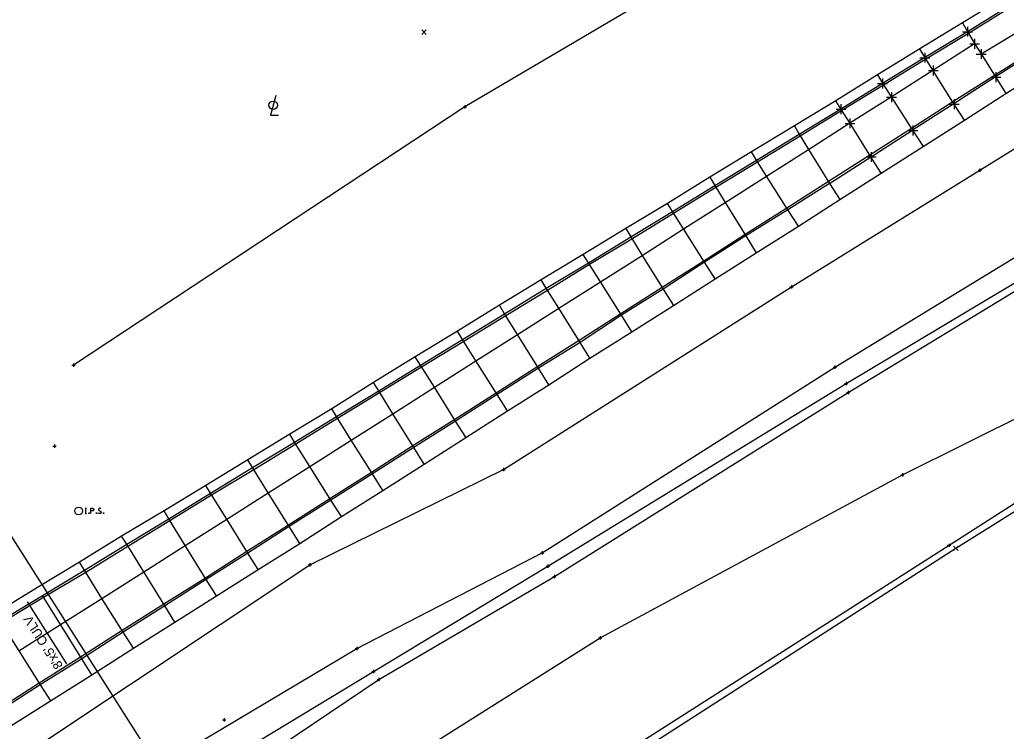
# Model space of a CAD drawing. Extents: x 207090 to 277928, y 600777 to 621109.
# Drawn here: x 261676.8 to 261977.3, y 611702.8 to 611919.6 of the extents above; entities that cross this region are included whole.
import ezdxf

# ---------------------------------------------------------------- set-up
doc = ezdxf.new("R2010")
doc.units = 0
for name, color, linetype in [('BR_X_SV_Abut', 7, 'Continuous'), ('DR_X_Culvert', 7, 'Continuous'), ('DR_X_Ditch', 7, 'Continuous'), ('DR_X_Text', 7, 'Continuous'), ('PM_P_Dotted_Line', 7, 'Continuous'), ('PM_P_Edge_Line', 7, 'Continuous'), ('PM_P_Lane_Line', 7, 'Continuous'), ('PM_P_Stop_Line', 7, 'Continuous'), ('PM_X_Edge_Line', 7, 'Continuous'), ('PV_X_EOP', 7, 'Continuous'), ('PV_X_Joint', 7, 'Continuous'), ('PV_X_Shoulder', 7, 'Continuous'), ('SC_ProfileRun2', 7, 'Continuous'), ('SV_X_LiDAR_Check_Spots', 7, 'Continuous'), ('SV_X_Terrain_Boundary', 7, 'Continuous'), ('SV_X_Toe_of_Slope', 7, 'Continuous')]:
    doc.layers.add(name, color=color, linetype=linetype)

msp = doc.modelspace()

# ---------------------------------------------------------------- linework, layer by layer
at = {"layer": 'BR_X_SV_Abut'}
msp.add_lwpolyline([(261754.78, 611896.47), (261753.2, 611890.49), (261755.57, 611890.49)], dxfattribs=at)
msp.add_circle((261753.99, 611893.52), 1.3, dxfattribs=at)
at = {"layer": 'DR_X_Culvert'}
msp.add_line((261715.99, 611696.51), (261667.47, 611772.86), dxfattribs=at)
at = {"layer": 'DR_X_Ditch'}
msp.add_lwpolyline([(261132.11, 611543.06), (261151.34, 611551.01), (261204.82, 611549.24), (261275.42, 611542.1), (261338.97, 611540.56), (261396.89, 611545.27), (261464.5, 611556.09), (261526.91, 611576.88), (261579.68, 611599.94), (261643.38, 611630.11), (261702.06, 611671.1), (261784.56, 611720.96), (261837.63, 611753.06), (261928.54, 611808.72), (261986.01, 611843.07), (262043.42, 611883.09), (262136.97, 611939.5), (262196.81, 611979.61), (262342.79, 612067.36), (262434.39, 612121.89), (262514.3, 612151.84), (262581.31, 612172.43), (262656.49, 612183.09)], dxfattribs=at)
at = {"layer": 'DR_X_Text'}
msp.add_line((261679.01, 611742.21), (261691, 611723.34), dxfattribs=at)
at = {"layer": 'PM_P_Dotted_Line'}
for points in [[(261696.72, 611770.7), (261697.08, 611770.7)], [(261696.72, 611769.1), (261697.08, 611769.1)], [(261696.9, 611769.1), (261696.9, 611770.7)], [(261697.86, 611769.31), (261697.92, 611769.31), (261697.95, 611769.28), (261697.98, 611769.23), (261697.98, 611769.17), (261697.95, 611769.12), (261697.92, 611769.1), (261697.86, 611769.1), (261697.83, 611769.12), (261697.79, 611769.17), (261697.79, 611769.23), (261697.83, 611769.28), (261697.86, 611769.31)], [(261698.47, 611769.1), (261698.47, 611770.7), (261699, 611770.7), (261699.05, 611770.68), (261699.13, 611770.66), (261699.16, 611770.63), (261699.19, 611770.61), (261699.24, 611770.54), (261699.27, 611770.48), (261699.29, 611770.38), (261699.29, 611770.23), (261699.28, 611770.18), (261699.26, 611770.1), (261699.22, 611770.02), (261699.17, 611769.98), (261699.14, 611769.95), (261699.08, 611769.93), (261699, 611769.91), (261698.47, 611769.91)], [(261700.11, 611769.31), (261700.16, 611769.31), (261700.2, 611769.28), (261700.23, 611769.23), (261700.23, 611769.17), (261700.2, 611769.12), (261700.16, 611769.1), (261700.11, 611769.1), (261700.08, 611769.12), (261700.04, 611769.17), (261700.04, 611769.23), (261700.08, 611769.28), (261700.11, 611769.31)], [(261701.48, 611770.58), (261701.45, 611770.61), (261701.42, 611770.63), (261701.32, 611770.67), (261701.2, 611770.7), (261701.11, 611770.7), (261701.08, 611770.7), (261700.94, 611770.66), (261700.81, 611770.58), (261700.74, 611770.48), (261700.72, 611770.38), (261700.72, 611770.3), (261700.74, 611770.2), (261700.83, 611770.12), (261701.43, 611769.74), (261701.49, 611769.69), (261701.51, 611769.64), (261701.53, 611769.56), (261701.53, 611769.49), (261701.52, 611769.41), (261701.51, 611769.36), (261701.49, 611769.3), (261701.46, 611769.25), (261701.44, 611769.21), (261701.41, 611769.17), (261701.38, 611769.15), (261701.33, 611769.12), (261701.3, 611769.11), (261701.2, 611769.1), (261701.05, 611769.1), (261700.95, 611769.12), (261700.8, 611769.21), (261700.72, 611769.28)], [(261702.29, 611769.31), (261702.35, 611769.31), (261702.38, 611769.28), (261702.41, 611769.23), (261702.41, 611769.17), (261702.38, 611769.12), (261702.35, 611769.1), (261702.29, 611769.1), (261702.26, 611769.12), (261702.23, 611769.17), (261702.23, 611769.23), (261702.26, 611769.28), (261702.29, 611769.31)]]:
    msp.add_lwpolyline(points, dxfattribs=at)
msp.add_circle((261694.71, 611769.89), 1.2, dxfattribs=at)
at = {"layer": 'PM_P_Edge_Line'}
for points in [[(261095.2, 611517.38), (261109.55, 611556.21), (261131.91, 611573.68), (261149.08, 611575.07), (261202.59, 611571.64), (261280.97, 611564.25), (261338.62, 611565.1), (261393.58, 611575.38), (261461.16, 611589.52), (261517.96, 611607.33), (261562.93, 611628.5), (261627.57, 611664.18), (261682.84, 611698.73), (261765.12, 611753.52), (261824.13, 611782.52), (261911.81, 611838.23), (261969.24, 611873.72), (262025.82, 611908.8), (262125.41, 611964.66), (262182.53, 612002.94), (262326.11, 612091.51)], [(261150.65, 611386.42), (261155.64, 611444.15), (261157.57, 611491.18), (261209.46, 611500.37), (261264.83, 611505.15), (261342.34, 611500.54), (261398.44, 611505.87), (261472.12, 611523.34), (261533.41, 611542.89), (261595.48, 611569.82), (261660.17, 611598), (261726.83, 611640.47), (261794.94, 611694.24), (261853.6, 611731.21), (261945.61, 611780.89), (262004.28, 611810.1), (262064.35, 611850.74), (262127.57, 611893.89), (262159.14, 611906.07), (262217.33, 611944.84), (262360.65, 612038.77)]]:
    msp.add_lwpolyline(points, dxfattribs=at)
at = {"layer": 'PM_P_Lane_Line'}
msp.add_lwpolyline([(261153.94, 611385.97), (261160.28, 611443.31), (261165.11, 611483.68), (261209.25, 611484.8), (261264.74, 611486.28), (261342.14, 611487.48), (261398.74, 611488.7), (261481.71, 611501.24), (261537, 611521.16), (261606, 611546.1), (261656.85, 611565.67), (261670.38, 611573.79), (261742.74, 611619.98), (261811.92, 611664.95), (261868.59, 611701.14), (261959.9, 611759.42), (262013.54, 611793.87), (262076.54, 611833.59), (262168.76, 611888.84), (262184.39, 611898.2), (262204.83, 611910.25), (262363.11, 611892.31)], dxfattribs=at)
at = {"layer": 'PM_P_Stop_Line'}
for p, q in [((261811.86, 611893.04), (261812.86, 611893.04)), ((261812.36, 611893.54), (261812.36, 611892.54)), ((261812.36, 611893.04), (261812.36, 611893.04)), ((261968.74, 611873.72), (261969.74, 611873.72)), ((261969.24, 611874.22), (261969.24, 611873.22)), ((261969.24, 611873.72), (261969.24, 611873.72)), ((261911.31, 611838.23), (261912.31, 611838.23)), ((261911.81, 611838.73), (261911.81, 611837.73)), ((261911.81, 611838.23), (261911.81, 611838.23)), ((261692.64, 611814.37), (261693.64, 611814.37)), ((261693.14, 611814.87), (261693.14, 611813.87)), ((261693.14, 611814.37), (261693.14, 611814.37)), ((261924.55, 611813.69), (261925.55, 611813.69)), ((261925.05, 611814.19), (261925.05, 611813.19)), ((261925.05, 611813.69), (261925.05, 611813.69)), ((261928.04, 611808.72), (261929.04, 611808.72)), ((261928.54, 611809.22), (261928.54, 611808.22)), ((261928.54, 611808.72), (261928.54, 611808.72)), ((261928.57, 611806.04), (261929.57, 611806.04)), ((261929.07, 611806.54), (261929.07, 611805.54)), ((261929.07, 611806.04), (261929.07, 611806.04)), ((261823.63, 611782.52), (261824.63, 611782.52)), ((261824.13, 611783.02), (261824.13, 611782.02)), ((261824.13, 611782.52), (261824.13, 611782.52)), ((261945.11, 611780.89), (261946.11, 611780.89)), ((261945.61, 611781.39), (261945.61, 611780.39)), ((261945.61, 611780.89), (261945.61, 611780.89)), ((261959.4, 611759.42), (261960.4, 611759.42)), ((261959.9, 611759.92), (261959.9, 611758.92)), ((261959.9, 611759.42), (261959.9, 611759.42)), ((261835.4, 611757.16), (261836.4, 611757.16)), ((261835.9, 611757.66), (261835.9, 611756.66)), ((261835.9, 611757.16), (261835.9, 611757.16)), ((261764.62, 611753.52), (261765.62, 611753.52)), ((261765.12, 611754.02), (261765.12, 611753.02)), ((261765.12, 611753.52), (261765.12, 611753.52)), ((261837.63, 611753.56), (261837.63, 611752.56)), ((261837.13, 611753.06), (261838.13, 611753.06)), ((261837.63, 611753.06), (261837.63, 611753.06)), ((261839.61, 611750.39), (261839.61, 611749.39)), ((261839.11, 611749.89), (261840.11, 611749.89)), ((261839.61, 611749.89), (261839.61, 611749.89)), ((261853.1, 611731.21), (261854.1, 611731.21)), ((261853.6, 611731.71), (261853.6, 611730.71)), ((261853.6, 611731.21), (261853.6, 611731.21)), ((261778.95, 611728.01), (261779.95, 611728.01)), ((261779.45, 611728.51), (261779.45, 611727.51)), ((261779.45, 611728.01), (261779.45, 611728.01)), ((261784.06, 611720.96), (261785.06, 611720.96)), ((261784.56, 611721.46), (261784.56, 611720.46)), ((261784.56, 611720.96), (261784.56, 611720.96)), ((261785.6, 611718.54), (261786.6, 611718.54)), ((261786.1, 611719.04), (261786.1, 611718.04)), ((261786.1, 611718.54), (261786.1, 611718.54))]:
    msp.add_line(p, q, dxfattribs=at)
at = {"layer": 'PM_X_Edge_Line'}
for p, q in [((261799.22, 611915.14), (261800.55, 611916.48)), ((261799.22, 611916.48), (261800.55, 611915.14)), ((261961.23, 611757.84), (261962.57, 611759.18)), ((261961.23, 611759.18), (261962.57, 611757.84))]:
    msp.add_line(p, q, dxfattribs=at)
for points in [[(261671.16, 611735.77), (261684, 611743.61), (261696.86, 611751.28), (261709.72, 611759.19), (261722.48, 611767.02), (261735.16, 611774.85), (261748.05, 611782.52), (261760.83, 611790.38), (261773.6, 611798.18), (261786.4, 611806.01), (261799.18, 611813.78), (261811.99, 611821.61), (261824.79, 611829.47), (261837.51, 611837.22), (261850.31, 611845.08), (261863.19, 611852.87), (261875.94, 611860.67), (261888.85, 611868.58), (261901.48, 611876.33), (261914.47, 611884.22), (261927.2, 611892.01), (261939.92, 611899.74), (261952.77, 611907.64), (261965.72, 611915.54), (261979.19, 611923.84)], [(261987.04, 611911.02), (261973.73, 611902.58), (261960.97, 611894.57), (261948.41, 611886.44), (261935.72, 611878.33), (261923.12, 611870.27), (261910.43, 611862.14), (261897.73, 611854.15), (261885.18, 611846.05), (261872.49, 611837.95), (261859.82, 611829.99), (261847.16, 611821.82), (261834.56, 611813.88), (261821.93, 611805.77), (261809.26, 611797.74), (261796.5, 611789.75), (261783.94, 611781.62), (261771.23, 611773.59), (261758.6, 611765.54), (261745.94, 611757.51), (261733.31, 611749.45), (261720.64, 611741.44), (261707.99, 611733.42), (261695.31, 611725.36), (261682.69, 611717.38), (261669.95, 611709.28)]]:
    msp.add_lwpolyline(points, dxfattribs=at)
at = {"layer": 'PV_X_EOP'}
for points in [[(261977.36, 611926.85), (261963.96, 611918.66), (261950.93, 611910.7), (261938.09, 611902.8), (261925.33, 611894.88), (261912.73, 611887.26), (261899.71, 611879.33), (261886.93, 611871.58), (261874.07, 611863.63), (261861.34, 611855.98), (261848.38, 611848.08), (261835.62, 611840.33), (261822.93, 611832.57), (261810.09, 611824.67), (261797.24, 611816.86), (261784.54, 611809.03), (261771.88, 611801.07), (261759.09, 611793.3), (261746.24, 611785.48), (261733.45, 611777.61), (261720.73, 611769.93), (261707.8, 611762.18), (261694.96, 611754.32), (261682.21, 611746.6), (261669.39, 611738.7)], [(261673.28, 611703.86), (261686.12, 611712.05), (261698.69, 611719.95), (261711.39, 611728.07), (261723.96, 611735.96), (261736.7, 611744.03), (261749.35, 611752.05), (261762.07, 611760.02), (261774.74, 611768.21), (261787.41, 611776.13), (261799.93, 611784.15), (261812.7, 611792.25), (261825.32, 611800.39), (261837.94, 611808.33), (261850.46, 611816.48), (261863.23, 611824.47), (261875.92, 611832.52), (261888.64, 611840.61), (261901.06, 611848.61), (261913.98, 611856.68), (261926.58, 611864.79), (261939.15, 611872.89), (261951.92, 611880.98), (261964.51, 611889), (261977.18, 611897.17), (261990.4, 611905.54)]]:
    msp.add_lwpolyline(points, dxfattribs=at)
at = {"layer": 'PV_X_Joint'}
msp.add_line((261923.45, 611869.73), (261948.72, 611885.95), dxfattribs=at)
for points in [[(261969.67, 611909.16), (261983.14, 611917.37), (261996.1, 611925.21), (262008.82, 611933.05), (262021.68, 611940.97), (262034.35, 611948.61), (262047.25, 611956.47), (262060.1, 611964.3), (262072.81, 611971.98), (262085.45, 611979.77), (262098.39, 611987.63), (262111.17, 611995.43), (262123.99, 612003.24), (262136.83, 612011.09), (262149.61, 612018.97), (262162.63, 612026.86), (262175.23, 612034.57), (262188.24, 612042.4), (262201.02, 612050.15), (262213.81, 612057.93), (262226.71, 612065.72), (262239.38, 612073.54)], [(262243.57, 612066.59), (262230.75, 612058.86), (262217.78, 612051.06), (262205.03, 612043.31), (262192.24, 612035.51), (262179.39, 612027.69), (262166.53, 612019.86), (262153.73, 612012.08), (262140.88, 612004.22), (262127.96, 611996.3), (262115.21, 611988.56), (262102.49, 611980.81), (262089.66, 611973.04), (262076.89, 611965.25), (262064.18, 611957.49), (262051.34, 611949.71), (262038.5, 611941.83), (262025.79, 611934.15), (262012.96, 611926.27), (262000.04, 611918.42), (261987.29, 611910.61), (261974, 611902.15), (261961.33, 611894), (261948.72, 611885.95)], [(261926.92, 611892.44), (261939.58, 611900.25), (261952.43, 611908.17), (261965.41, 611916.06), (261978.9, 611924.32)], [(261963.96, 611918.66), (261965.41, 611916.06), (261967.62, 611912.4), (261969.67, 611909.16), (261974, 611902.15), (261977.18, 611897.17)], [(261676.53, 611727.24), (261689.15, 611735.26), (261701.8, 611743.24), (261714.57, 611751.34), (261727.17, 611759.36), (261739.83, 611767.41), (261752.48, 611775.39), (261765.13, 611783.45), (261777.76, 611791.47), (261790.38, 611799.52), (261803.08, 611807.62), (261815.72, 611815.67), (261828.43, 611823.69), (261841.01, 611831.72), (261853.67, 611839.68), (261866.33, 611847.77), (261879, 611855.85), (261891.69, 611863.93), (261904.25, 611871.96), (261917.03, 611880.09), (261929.62, 611888.16), (261942.25, 611896.15), (261954.93, 611904.24), (261967.62, 611912.4)], [(261964.51, 611889), (261961.33, 611894), (261954.93, 611904.24), (261952.43, 611908.17), (261950.93, 611910.7)], [(261938.09, 611902.8), (261939.58, 611900.25), (261942.25, 611896.15), (261948.72, 611885.95), (261951.92, 611880.98)], [(261939.15, 611872.89), (261936.04, 611877.81), (261929.62, 611888.16), (261926.92, 611892.44), (261925.33, 611894.88)], [(261670.85, 611736.27), (261683.69, 611744.1), (261696.49, 611751.89), (261709.38, 611759.74), (261722.15, 611767.54), (261734.87, 611775.31), (261747.69, 611783.1), (261760.5, 611790.91), (261773.28, 611798.7), (261786.1, 611806.49), (261798.85, 611814.31), (261811.68, 611822.1), (261824.47, 611829.97), (261837.16, 611837.76), (261850.01, 611845.56), (261862.86, 611853.39), (261875.62, 611861.17), (261888.54, 611869.07), (261901.21, 611876.76), (261914.16, 611884.72), (261926.92, 611892.44)], [(261912.73, 611887.26), (261914.16, 611884.72), (261917.03, 611880.09), (261923.45, 611869.73), (261926.58, 611864.79)], [(261913.98, 611856.68), (261910.72, 611861.68), (261904.25, 611871.96), (261901.21, 611876.76), (261899.71, 611879.33)], [(261886.93, 611871.58), (261888.54, 611869.07), (261891.69, 611863.93), (261897.96, 611853.76), (261901.06, 611848.61)], [(261923.45, 611869.73), (261910.72, 611861.68), (261897.96, 611853.76), (261885.39, 611845.72), (261872.79, 611837.48), (261860.08, 611829.58), (261847.49, 611821.28), (261834.82, 611813.46), (261822.17, 611805.38), (261809.54, 611797.29), (261796.82, 611789.24), (261784.21, 611781.2), (261771.5, 611773.16), (261758.87, 611765.11), (261746.2, 611757.08), (261733.58, 611749.02), (261720.92, 611740.98), (261708.28, 611732.97), (261695.66, 611724.79), (261683.01, 611716.86), (261670.27, 611708.76)], [(261888.64, 611840.61), (261885.39, 611845.72), (261879, 611855.85), (261875.62, 611861.17), (261874.07, 611863.63)], [(261861.34, 611855.98), (261862.86, 611853.39), (261866.33, 611847.77), (261872.79, 611837.48), (261875.92, 611832.52)], [(261863.23, 611824.47), (261860.08, 611829.58), (261853.67, 611839.68), (261850.01, 611845.56), (261848.38, 611848.08)], [(261850.46, 611816.48), (261847.49, 611821.28), (261841.01, 611831.72), (261837.16, 611837.76), (261835.62, 611840.33)], [(261837.94, 611808.33), (261834.82, 611813.46), (261828.43, 611823.69), (261824.47, 611829.97), (261822.93, 611832.57)], [(261825.32, 611800.39), (261822.17, 611805.38), (261815.72, 611815.67), (261811.68, 611822.1), (261810.09, 611824.67)], [(261812.7, 611792.35), (261809.54, 611797.29), (261803.08, 611807.62), (261798.85, 611814.31), (261797.24, 611816.86)], [(261799.93, 611784.15), (261796.82, 611789.24), (261790.38, 611799.52), (261786.1, 611806.49), (261784.54, 611809.03)], [(261787.41, 611776.13), (261784.21, 611781.2), (261777.76, 611791.47), (261773.28, 611798.7), (261771.88, 611801.07)], [(261774.74, 611768.21), (261771.5, 611773.16), (261765.13, 611783.45), (261760.5, 611790.91), (261759.09, 611793.3)], [(261762.07, 611760.02), (261758.87, 611765.11), (261752.48, 611775.39), (261747.69, 611783.1), (261746.24, 611785.48)], [(261749.35, 611752.05), (261746.2, 611757.08), (261739.83, 611767.41), (261734.87, 611775.31), (261733.45, 611777.61)], [(261736.7, 611744.03), (261733.58, 611749.02), (261727.17, 611759.36), (261722.15, 611767.54), (261720.73, 611769.93)], [(261723.96, 611735.96), (261720.92, 611740.98), (261714.57, 611751.34), (261709.38, 611759.74), (261707.8, 611762.18)], [(261711.39, 611728.07), (261708.28, 611732.97), (261701.8, 611743.24), (261696.49, 611751.89), (261694.96, 611754.32)], [(261698.69, 611719.95), (261695.66, 611724.79), (261689.15, 611735.26), (261683.69, 611744.1)], [(261670.85, 611736.27), (261676.53, 611727.24), (261683.01, 611716.86), (261686.12, 611712.05)]]:
    msp.add_lwpolyline(points, dxfattribs=at)
at = {"layer": 'PV_X_Shoulder'}
msp.add_line((261969.67, 611909.16), (261969.64, 611909.14), dxfattribs=at)
at = {"layer": 'SC_ProfileRun2'}
for p, q in [((261686.84, 611789.68), (261687.84, 611789.68)), ((261687.34, 611790.18), (261687.34, 611789.18)), ((261687.34, 611789.68), (261687.34, 611789.68)), ((261738.54, 611706.2), (261739.54, 611706.2)), ((261739.04, 611706.7), (261739.04, 611705.7)), ((261739.04, 611706.2), (261739.04, 611706.2))]:
    msp.add_line(p, q, dxfattribs=at)
at = {"layer": 'SV_X_LiDAR_Check_Spots'}
for p, q in [((261963.95, 611915.96), (261966.95, 611915.96)), ((261965.45, 611917.46), (261965.45, 611914.46)), ((261965.45, 611915.96), (261965.45, 611915.96)), ((261967.63, 611913.78), (261967.63, 611910.78)), ((261952.47, 611909.54), (261952.47, 611906.54)), ((261966.13, 611912.28), (261969.13, 611912.28)), ((261967.63, 611912.28), (261967.63, 611912.28)), ((261969.64, 611910.64), (261969.64, 611907.64)), ((261950.97, 611908.04), (261953.97, 611908.04)), ((261952.47, 611908.04), (261952.47, 611908.04)), ((261968.14, 611909.14), (261971.14, 611909.14)), ((261969.64, 611909.14), (261969.64, 611909.14)), ((261953.54, 611904.15), (261956.54, 611904.15)), ((261955.04, 611905.65), (261955.04, 611902.65)), ((261955.04, 611904.15), (261955.04, 611904.15)), ((261974.07, 611903.58), (261974.07, 611900.58)), ((261939.56, 611901.65), (261939.56, 611898.65)), ((261972.57, 611902.08), (261975.57, 611902.08)), ((261974.07, 611902.08), (261974.07, 611902.08)), ((261938.06, 611900.15), (261941.06, 611900.15)), ((261939.56, 611900.15), (261939.56, 611900.15)), ((261942.29, 611897.52), (261942.29, 611894.52)), ((261940.79, 611896.02), (261943.79, 611896.02)), ((261942.29, 611896.02), (261942.29, 611896.02)), ((261961.4, 611895.37), (261961.4, 611892.37)), ((261925.41, 611892.37), (261928.41, 611892.37)), ((261926.91, 611893.87), (261926.91, 611890.87)), ((261926.91, 611892.37), (261926.91, 611892.37)), ((261959.9, 611893.87), (261962.9, 611893.87)), ((261961.4, 611893.87), (261961.4, 611893.87)), ((261929.65, 611889.51), (261929.65, 611886.51)), ((261928.15, 611888.01), (261931.15, 611888.01)), ((261929.65, 611888.01), (261929.65, 611888.01)), ((261947.29, 611885.83), (261950.29, 611885.83)), ((261948.79, 611887.33), (261948.79, 611884.33)), ((261948.79, 611885.83), (261948.79, 611885.83)), ((261934.66, 611877.78), (261937.66, 611877.78)), ((261936.16, 611879.28), (261936.16, 611876.28)), ((261936.16, 611877.78), (261936.16, 611877.78))]:
    msp.add_line(p, q, dxfattribs=at)
at = {"layer": 'SV_X_Terrain_Boundary'}
msp.add_lwpolyline([(261670.38, 611573.79), (261744.36, 611617.34), (261814.33, 611663.74), (261869.18, 611698.9), (261961.9, 611758.51), (262015.3, 611791.96), (262079.06, 611831.97), (262076.54, 611833.59), (262168.76, 611888.84), (262184.39, 611898.2), (262204.83, 611910.25), (262363.11, 611892.31)], dxfattribs=at)
at = {"layer": 'SV_X_Toe_of_Slope'}
for points in [[(261729.51, 611698.17), (261779.45, 611728.01), (261835.9, 611757.16), (261925.05, 611813.69), (261983.11, 611849.16), (262040.29, 611887.78), (262135.2, 611943.79), (262193.94, 611983.59), (262339.69, 612072.56), (262431.52, 612127.67), (262513.25, 612156.24), (262580.26, 612177.17), (262655.37, 612187.35)], [(261135.4, 611543.42), (261151.99, 611545.22), (261205.95, 611544.69), (261267.18, 611537.07), (261340.59, 611536.02), (261398.29, 611542.06), (261464.98, 611551.3), (261527.41, 611569.91), (261584.17, 611593.02), (261647.78, 611623.35), (261706.85, 611665.06), (261786.1, 611718.54), (261839.61, 611749.89), (261929.07, 611806.04), (261986.89, 611841.11), (262047.29, 611878.6), (262138.86, 611935.4), (262200.14, 611972.99), (262344.06, 612064.28), (262436.85, 612118.36), (262514.09, 612148.95), (262582.72, 612168.49), (262657.34, 612178.41)], [(262283.04, 612168.99), (262271.51, 612147.23), (262176.6, 612102.62), (262080.36, 612054.77), (261984.45, 612003.37), (261899.63, 611944.52), (261812.36, 611893.04), (261693.14, 611814.37)]]:
    msp.add_lwpolyline(points, dxfattribs=at)

# ---------------------------------------------------------------- texts
at = {"layer": 'DR_X_Text'}
msp.add_text("8'x5' CULV", height=2.8, rotation=122.4417, dxfattribs=at).set_placement((261690.05, 611722.79))

doc.saveas('drawing.dxf')
